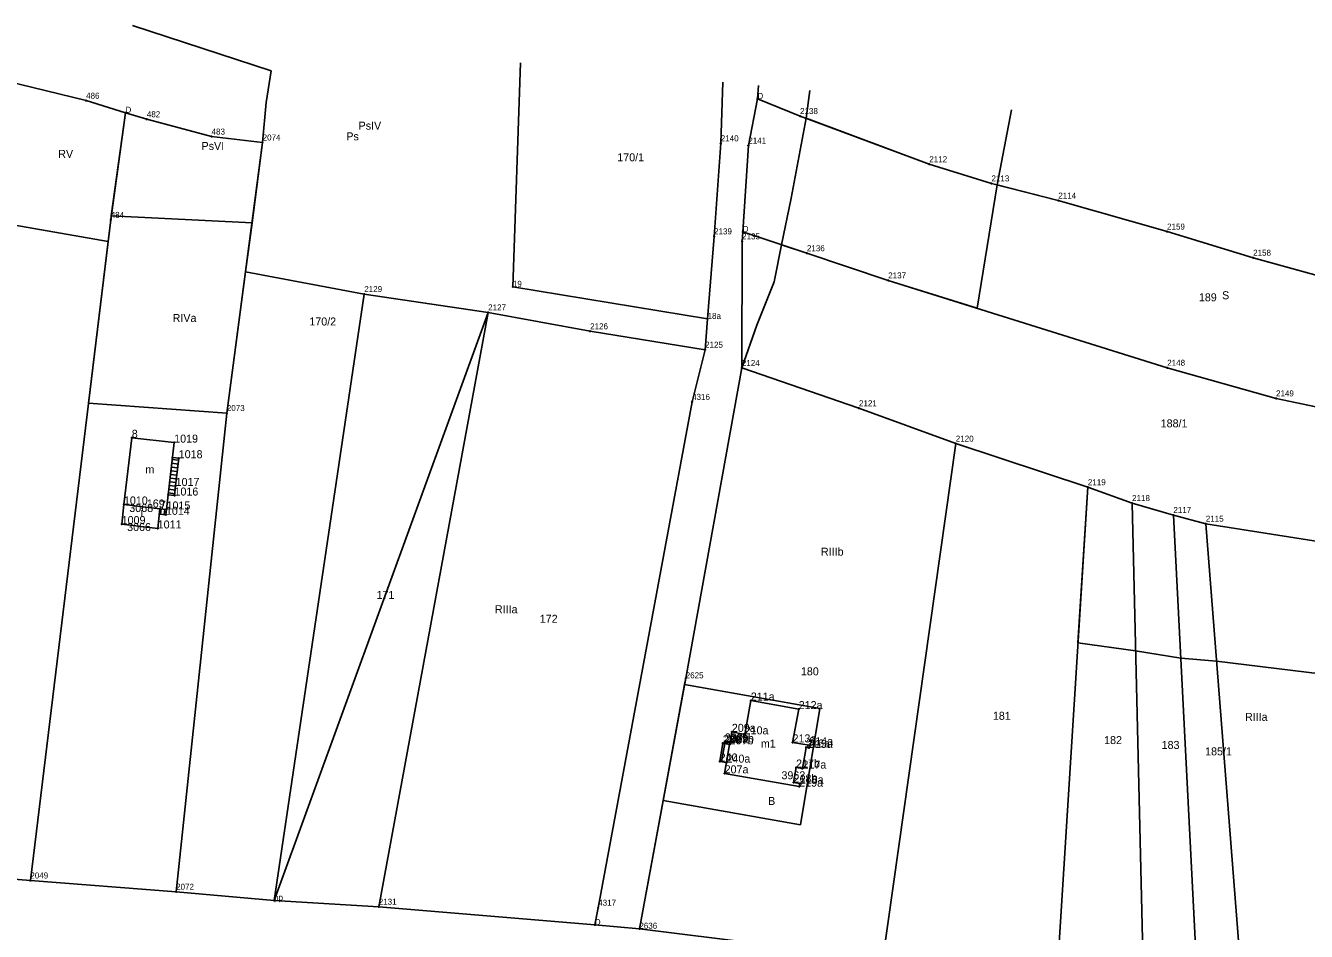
# Model space of a CAD drawing. Extents: x 7467189 to 7469366, y 5491487 to 5492734.
# Drawn here: x 7468314 to 7468554, y 5491683.5 to 5491853.3 of the extents above; entities that cross this region are included whole.
import ezdxf

# ---------------------------------------------------------------- set-up
doc = ezdxf.new("R2010")
doc.units = 0
for name, color, linetype in [('203-punkt graniczny', 7, 'Continuous'), ('203-punkt graniczny-Atr103', 7, 'Continuous'), ('209-oznaczenie konturu klasyfikacyjnego', 7, 'Continuous'), ('210-oznaczenie konturu użytku gruntowego', 7, 'Continuous'), ('211-numer działki ewidencyjnej', 7, 'Continuous'), ('217-kontur klasyfikacyjny', 7, 'Continuous'), ('218-kontur użytku gruntowego', 7, 'Continuous'), ('219-działka ewidencyjna', 7, 'Continuous'), ('312-budynek ewidencyjny', 7, 'Continuous'), ('312-oznaczenie budynku ewidencyjnego', 7, 'Continuous'), ('312-oznaczenie budynku ewidencyjnego-Atr117', 7, 'Continuous'), ('352-schody', 7, 'Continuous'), ('Punkt budynku', 7, 'Continuous'), ('Punkt budynku-Atr103', 7, 'Continuous'), ('Punkt budynku-Atr104', 7, 'Continuous')]:
    doc.layers.add(name, color=color, linetype=linetype)

# ---------------------------------------------------------------- blocks, each defined once
blk = doc.blocks.new('203')
blk.add_circle((0, 0), 0.09)
blk = doc.blocks.new('PUNKTBUD')
blk.add_circle((0, 0), 0.09)

msp = doc.modelspace()

# ---------------------------------------------------------------- linework, layer by layer
at = {"layer": '217-kontur klasyfikacyjny'}
for points in [[(7468360, 5491844.81), (7468334.03, 5491853.28)], [(7468359.08, 5491838.84), (7468360, 5491844.81)], [(7468325.31, 5491839.21), (7468305.25, 5491844.1)], [(7468444.27, 5491831.21), (7468444.64, 5491842.68)], [(7468451.37, 5491842.04), (7468451.15, 5491839.55)], [(7468460.26, 5491835.9), (7468460.95, 5491841.12)], [(7468332.7, 5491836.95), (7468325.31, 5491839.21)], [(7468358.4, 5491831.36), (7468359.08, 5491838.84)], [(7468451.15, 5491839.55), (7468449.44, 5491830.8)], [(7468498.74, 5491837.5), (7468496.08, 5491823.41)], [(7468330.03, 5491817.61), (7468332.7, 5491836.95)], [(7468332.7, 5491836.95), (7468336.69, 5491835.73)], [(7468336.69, 5491835.73), (7468348.83, 5491832.47)], [(7468457.45, 5491820.92), (7468460.26, 5491835.9)], [(7468348.83, 5491832.47), (7468358.4, 5491831.36)], [(7468358.4, 5491831.36), (7468356.41, 5491816.33)], [(7468443.02, 5491813.77), (7468444.27, 5491831.21)], [(7468449.44, 5491830.8), (7468448.39, 5491814.61)], [(7468496.08, 5491823.41), (7468492.35, 5491800.28)], [(7468455.67, 5491812.18), (7468457.45, 5491820.92)], [(7468301.54, 5491817.66), (7468329.45, 5491812.82)], [(7468329.45, 5491812.82), (7468329.93, 5491816.85)], [(7468329.93, 5491816.85), (7468330.03, 5491817.61)], [(7468356.41, 5491816.33), (7468330.03, 5491817.61)], [(7468356.41, 5491816.33), (7468355.19, 5491807.11)], [(7468441.8, 5491798.29), (7468443.02, 5491813.77)], [(7468448.39, 5491814.61), (7468448.27, 5491812.82)], [(7468329.45, 5491812.82), (7468325.75, 5491782.52)], [(7468448.27, 5491812.82), (7468448.23, 5491789.1)], [(7468454.25, 5491805.23), (7468455.67, 5491812.18)], [(7468460.42, 5491810.6), (7468455.67, 5491812.18)], [(7468475.66, 5491805.51), (7468460.42, 5491810.6)], [(7468351.69, 5491780.64), (7468355.19, 5491807.11)], [(7468355.19, 5491807.11), (7468377.45, 5491802.96)], [(7468451.04, 5491797.12), (7468454.25, 5491805.23)], [(7468492.35, 5491800.28), (7468475.66, 5491805.51)], [(7468377.45, 5491802.96), (7468400.67, 5491799.5)], [(7468400.67, 5491799.5), (7468360.54, 5491689.28)], [(7468419.79, 5491795.97), (7468400.67, 5491799.5)], [(7468441.33, 5491792.52), (7468441.8, 5491798.29)], [(7468448.23, 5491789.1), (7468451.04, 5491797.12)], [(7468441.33, 5491792.52), (7468419.79, 5491795.97)], [(7468438.9, 5491782.75), (7468441.33, 5491792.52)], [(7468448.23, 5491789.1), (7468437.7, 5491730.92)], [(7468470.18, 5491781.55), (7468448.23, 5491789.1)], [(7468325.75, 5491782.52), (7468351.69, 5491780.64)], [(7468421.3, 5491687.9), (7468438.9, 5491782.75)], [(7468488.32, 5491774.91), (7468470.18, 5491781.55)], [(7468488.32, 5491774.91), (7468474.63, 5491678.26)], [(7468513.08, 5491766.75), (7468488.32, 5491774.91)], [(7468511.23, 5491737.54), (7468513.08, 5491766.75)], [(7468521.37, 5491763.76), (7468513.08, 5491766.75)], [(7468529.11, 5491761.53), (7468521.37, 5491763.76)], [(7468535.19, 5491759.89), (7468529.11, 5491761.53)], [(7468603.08, 5491749.2), (7468535.19, 5491759.89)], [(7468522.03, 5491736.04), (7468511.23, 5491737.54)], [(7468530.49, 5491734.7), (7468522.03, 5491736.04)], [(7468537.21, 5491734.14), (7468530.49, 5491734.7)], [(7468604.7, 5491725.89), (7468537.21, 5491734.14)], [(7468437.7, 5491730.92), (7468437.49, 5491729.78)], [(7468437.49, 5491729.78), (7468462.82, 5491725.23)], [(7468462.82, 5491725.23), (7468459.23, 5491703.47)], [(7468433.47, 5491708.03), (7468429.01, 5491683.98)], [(7468459.23, 5491703.47), (7468433.47, 5491708.03)], [(7468278.14, 5491695.95), (7468314.86, 5491693.01)], [(7468314.86, 5491693.01), (7468342.18, 5491690.9)], [(7468342.18, 5491690.9), (7468360.54, 5491689.28)], [(7468360.54, 5491689.28), (7468380.16, 5491688.08)], [(7468380.16, 5491688.08), (7468420.67, 5491684.68)], [(7468420.67, 5491684.68), (7468421.3, 5491687.9)], [(7468429.01, 5491683.98), (7468474.63, 5491678.26)]]:
    msp.add_lwpolyline(points, dxfattribs=at)
at = {"layer": '218-kontur użytku gruntowego'}
for points in [[(7468305.25, 5491844.1), (7468325.31, 5491839.21)], [(7468444.27, 5491831.21), (7468444.64, 5491842.68)], [(7468451.37, 5491842.04), (7468451.15, 5491839.55)], [(7468460.26, 5491835.9), (7468460.95, 5491841.12)], [(7468325.31, 5491839.21), (7468332.7, 5491836.95)], [(7468451.15, 5491839.55), (7468449.44, 5491830.8)], [(7468332.7, 5491836.95), (7468330.03, 5491817.61)], [(7468457.45, 5491820.92), (7468460.26, 5491835.9)], [(7468483.36, 5491827.3), (7468460.26, 5491835.9)], [(7468443.02, 5491813.77), (7468444.27, 5491831.21)], [(7468449.44, 5491830.8), (7468448.39, 5491814.61)], [(7468495.01, 5491823.69), (7468483.36, 5491827.3)], [(7468496.08, 5491823.41), (7468495.01, 5491823.69)], [(7468507.54, 5491820.47), (7468496.08, 5491823.41)], [(7468455.67, 5491812.18), (7468457.45, 5491820.92)], [(7468527.92, 5491814.67), (7468507.54, 5491820.47)], [(7468330.03, 5491817.61), (7468356.41, 5491816.33)], [(7468356.41, 5491816.33), (7468355.19, 5491807.11)], [(7468441.8, 5491798.29), (7468443.02, 5491813.77)], [(7468448.39, 5491814.61), (7468448.27, 5491812.82)], [(7468544.06, 5491809.76), (7468527.92, 5491814.67)], [(7468448.27, 5491812.82), (7468448.23, 5491789.1)], [(7468454.25, 5491805.23), (7468455.67, 5491812.18)], [(7468455.67, 5491812.18), (7468460.42, 5491810.6)], [(7468460.42, 5491810.6), (7468475.66, 5491805.51)], [(7468563.32, 5491804.43), (7468544.06, 5491809.76)], [(7468355.19, 5491807.11), (7468377.45, 5491802.96)], [(7468451.04, 5491797.12), (7468454.25, 5491805.23)], [(7468475.66, 5491805.51), (7468527.96, 5491789.12)], [(7468377.45, 5491802.96), (7468400.67, 5491799.5)], [(7468400.67, 5491799.5), (7468419.79, 5491795.97)], [(7468441.33, 5491792.52), (7468441.8, 5491798.29)], [(7468448.23, 5491789.1), (7468451.04, 5491797.12)], [(7468419.79, 5491795.97), (7468441.33, 5491792.52)], [(7468438.9, 5491782.75), (7468441.33, 5491792.52)], [(7468437.7, 5491730.92), (7468448.23, 5491789.1)], [(7468527.96, 5491789.12), (7468548.35, 5491783.39)], [(7468421.3, 5491687.9), (7468438.9, 5491782.75)], [(7468548.35, 5491783.39), (7468561.18, 5491780.71)], [(7468437.49, 5491729.78), (7468433.47, 5491708.03)], [(7468437.49, 5491729.78), (7468437.7, 5491730.92)], [(7468462.82, 5491725.23), (7468437.49, 5491729.78)], [(7468459.23, 5491703.47), (7468462.82, 5491725.23)], [(7468429.01, 5491683.98), (7468433.47, 5491708.03)], [(7468433.47, 5491708.03), (7468459.23, 5491703.47)], [(7468278.14, 5491695.95), (7468314.86, 5491693.01)], [(7468314.86, 5491693.01), (7468342.18, 5491690.9)], [(7468342.18, 5491690.9), (7468360.54, 5491689.28)], [(7468360.54, 5491689.28), (7468380.16, 5491688.08)], [(7468380.16, 5491688.08), (7468420.67, 5491684.68)], [(7468420.67, 5491684.68), (7468421.3, 5491687.9)], [(7468474.63, 5491678.26), (7468429.01, 5491683.98)]]:
    msp.add_lwpolyline(points, dxfattribs=at)
at = {"layer": '219-działka ewidencyjna'}
for points in [[(7468405.31, 5491804.31), (7468406.72, 5491846.32)], [(7468305.25, 5491844.1), (7468325.31, 5491839.21)], [(7468444.27, 5491831.21), (7468444.64, 5491842.68)], [(7468451.15, 5491839.55), (7468451.37, 5491842.04)], [(7468332.7, 5491836.95), (7468325.31, 5491839.21)], [(7468451.15, 5491839.55), (7468449.44, 5491830.8)], [(7468451.15, 5491839.55), (7468459.13, 5491836.32)], [(7468332.7, 5491836.95), (7468329.93, 5491816.85)], [(7468332.7, 5491836.95), (7468336.69, 5491835.73)], [(7468336.69, 5491835.73), (7468348.83, 5491832.47)], [(7468459.13, 5491836.32), (7468483.36, 5491827.3)], [(7468348.83, 5491832.47), (7468358.4, 5491831.36)], [(7468351.69, 5491780.64), (7468358.4, 5491831.36)], [(7468443.02, 5491813.77), (7468444.27, 5491831.21)], [(7468448.39, 5491814.61), (7468449.44, 5491830.8)], [(7468483.36, 5491827.3), (7468495.01, 5491823.69)], [(7468495.01, 5491823.69), (7468507.54, 5491820.47)], [(7468507.54, 5491820.47), (7468527.92, 5491814.67)], [(7468314.86, 5491693.01), (7468329.93, 5491816.85)], [(7468441.8, 5491798.29), (7468443.02, 5491813.77)], [(7468448.27, 5491812.82), (7468448.39, 5491814.61)], [(7468448.39, 5491814.61), (7468460.42, 5491810.6)], [(7468527.92, 5491814.67), (7468544.06, 5491809.76)], [(7468448.23, 5491789.1), (7468448.27, 5491812.82)], [(7468460.42, 5491810.6), (7468475.66, 5491805.51)], [(7468544.06, 5491809.76), (7468565.4, 5491803.85)], [(7468405.31, 5491804.31), (7468441.8, 5491798.29)], [(7468475.66, 5491805.51), (7468527.96, 5491789.12)], [(7468360.54, 5491689.28), (7468377.45, 5491802.96)], [(7468377.45, 5491802.96), (7468400.67, 5491799.5)], [(7468380.16, 5491688.08), (7468400.67, 5491799.5)], [(7468400.67, 5491799.5), (7468419.79, 5491795.97)], [(7468441.8, 5491798.29), (7468441.33, 5491792.52)], [(7468419.79, 5491795.97), (7468441.33, 5491792.52)], [(7468438.9, 5491782.75), (7468441.33, 5491792.52)], [(7468437.7, 5491730.92), (7468448.23, 5491789.1)], [(7468448.23, 5491789.1), (7468470.18, 5491781.55)], [(7468527.96, 5491789.12), (7468548.35, 5491783.39)], [(7468421.3, 5491687.9), (7468438.9, 5491782.75)], [(7468548.35, 5491783.39), (7468565.6, 5491779.78)], [(7468342.18, 5491690.9), (7468351.69, 5491780.64)], [(7468470.18, 5491781.55), (7468488.32, 5491774.91)], [(7468474.63, 5491678.26), (7468488.32, 5491774.91)], [(7468488.32, 5491774.91), (7468513.08, 5491766.75)], [(7468507.3, 5491675.36), (7468513.08, 5491766.75)], [(7468513.08, 5491766.75), (7468521.37, 5491763.76)], [(7468521.37, 5491763.76), (7468523.49, 5491674.08)], [(7468521.37, 5491763.76), (7468529.11, 5491761.53)], [(7468529.11, 5491761.53), (7468533.64, 5491673.4)], [(7468529.11, 5491761.53), (7468535.19, 5491759.89)], [(7468535.19, 5491759.89), (7468542, 5491672.98)], [(7468535.19, 5491759.89), (7468603.08, 5491749.2)], [(7468429.01, 5491683.98), (7468437.7, 5491730.92)], [(7468278.14, 5491695.95), (7468314.86, 5491693.01)], [(7468314.86, 5491693.01), (7468342.18, 5491690.9)], [(7468360.54, 5491689.28), (7468342.18, 5491690.9)], [(7468360.54, 5491689.28), (7468380.16, 5491688.08)], [(7468420.67, 5491684.68), (7468380.16, 5491688.08)], [(7468420.67, 5491684.68), (7468421.3, 5491687.9)], [(7468420.67, 5491684.68), (7468429.01, 5491683.98)], [(7468429.01, 5491683.98), (7468474.63, 5491678.26)]]:
    msp.add_lwpolyline(points, dxfattribs=at)
at = {"layer": '312-budynek ewidencyjny'}
for points in [[(7468332.4, 5491763.51), (7468333.87, 5491776.01)], [(7468333.87, 5491776.01), (7468341.82, 5491775.1)], [(7468341.82, 5491775.1), (7468340.39, 5491762.57)], [(7468331.98, 5491759.83), (7468332.4, 5491763.51)], [(7468332.4, 5491763.51), (7468339.16, 5491762.71)], [(7468339.16, 5491762.71), (7468332.4, 5491763.51)], [(7468339.16, 5491762.71), (7468338.73, 5491759.01)], [(7468340.39, 5491762.57), (7468339.16, 5491762.71)], [(7468338.73, 5491759.01), (7468331.98, 5491759.83)], [(7468448.76, 5491720.41), (7468449.91, 5491726.75)], [(7468449.91, 5491726.75), (7468458.88, 5491725.14)], [(7468458.88, 5491725.14), (7468457.73, 5491718.9)], [(7468446.01, 5491718.92), (7468446.35, 5491720.88)], [(7468446.35, 5491720.88), (7468448.76, 5491720.41)], [(7468444.97, 5491718.71), (7468445.03, 5491719.09)], [(7468445.94, 5491718.53), (7468444.97, 5491718.71)], [(7468445, 5491713.1), (7468445.94, 5491718.53)], [(7468445.03, 5491719.09), (7468446.01, 5491718.92)], [(7468457.73, 5491718.9), (7468460.87, 5491718.38)], [(7468460.28, 5491717.97), (7468459.59, 5491713.99)], [(7468460.79, 5491717.88), (7468460.28, 5491717.97)], [(7468460.87, 5491718.38), (7468460.79, 5491717.88)], [(7468458.98, 5491710.61), (7468445, 5491713.1)], [(7468458.4, 5491714.19), (7468457.91, 5491711.39)], [(7468459.59, 5491713.99), (7468458.4, 5491714.19)], [(7468457.91, 5491711.39), (7468459.09, 5491711.19)], [(7468459.09, 5491711.19), (7468458.98, 5491710.61)]]:
    msp.add_lwpolyline(points, dxfattribs=at)
at = {"layer": '352-schody'}
for points in [[(7468341.5, 5491772.31), (7468342.67, 5491772.18), (7468342.09, 5491766.98), (7468341.88, 5491765.18), (7468340.7, 5491765.31)], [(7468341.5, 5491772.31), (7468342.67, 5491772.18), (7468342.09, 5491766.98), (7468341.88, 5491765.18), (7468340.7, 5491765.31)], [(7468340.39, 5491762.57), (7468340.27, 5491761.57), (7468339.04, 5491761.7), (7468339.16, 5491762.71)], [(7468340.39, 5491762.57), (7468340.27, 5491761.57), (7468339.04, 5491761.7), (7468339.16, 5491762.71)], [(7468445.35, 5491715.11), (7468444.07, 5491715.33), (7468444.66, 5491718.75), (7468444.97, 5491718.71), (7468445.94, 5491718.53)], [(7468445.35, 5491715.11), (7468444.07, 5491715.33), (7468444.66, 5491718.75), (7468444.97, 5491718.71), (7468445.94, 5491718.53)]]:
    msp.add_lwpolyline(points, close=True, dxfattribs=at)
for points in [[(7468342.47, 5491770.4), (7468341.3, 5491770.53)], [(7468342.55, 5491771.09), (7468341.38, 5491771.23)], [(7468342.63, 5491771.79), (7468341.46, 5491771.92)], [(7468342.16, 5491767.61), (7468340.98, 5491767.75)], [(7468342.24, 5491768.31), (7468341.06, 5491768.44)], [(7468342.32, 5491769), (7468341.14, 5491769.14)], [(7468342.39, 5491769.7), (7468341.22, 5491769.83)], [(7468341.92, 5491765.53), (7468340.74, 5491765.66)], [(7468342, 5491766.22), (7468340.82, 5491766.36)], [(7468342.08, 5491766.92), (7468340.9, 5491767.05)], [(7468339.35, 5491762.69), (7468339.23, 5491761.68)], [(7468340.04, 5491762.61), (7468339.93, 5491761.61)], [(7468444.42, 5491715.27), (7468445.01, 5491718.7)]]:
    msp.add_lwpolyline(points, dxfattribs=at)

# ---------------------------------------------------------------- block references
at = {"layer": '203-punkt graniczny'}
for p in [(7468325.31, 5491839.21), (7468451.15, 5491839.55), (7468332.7, 5491836.95), (7468336.69, 5491835.73), (7468459.13, 5491836.32), (7468348.83, 5491832.47), (7468358.4, 5491831.36), (7468444.27, 5491831.21), (7468449.44, 5491830.8), (7468483.36, 5491827.3), (7468495.01, 5491823.69), (7468507.54, 5491820.47), (7468329.93, 5491816.85), (7468443.02, 5491813.77), (7468448.39, 5491814.61), (7468527.92, 5491814.67), (7468448.27, 5491812.82), (7468460.42, 5491810.6), (7468544.06, 5491809.76), (7468405.31, 5491804.31), (7468475.66, 5491805.51), (7468377.45, 5491802.96), (7468400.67, 5491799.5), (7468441.8, 5491798.29), (7468419.79, 5491795.97), (7468441.33, 5491792.52), (7468448.23, 5491789.1), (7468527.96, 5491789.12), (7468438.9, 5491782.75), (7468548.35, 5491783.39), (7468351.69, 5491780.64), (7468470.18, 5491781.55), (7468488.32, 5491774.91), (7468513.08, 5491766.75), (7468521.37, 5491763.76), (7468529.11, 5491761.53), (7468535.19, 5491759.89), (7468437.7, 5491730.92), (7468314.86, 5491693.01), (7468342.18, 5491690.9), (7468360.54, 5491689.28), (7468380.16, 5491688.08), (7468421.3, 5491687.9), (7468420.67, 5491684.68), (7468429.01, 5491683.98)]:
    msp.add_blockref('203', p, dxfattribs=at)
at = {"layer": 'Punkt budynku'}
for p in [(7468333.87, 5491776.01), (7468341.82, 5491775.1), (7468341.5, 5491772.31), (7468342.67, 5491772.18), (7468340.7, 5491765.31), (7468341.88, 5491765.18), (7468342.09, 5491766.98), (7468332.4, 5491763.51), (7468339.04, 5491761.7), (7468339.16, 5491762.71), (7468340.27, 5491761.57), (7468340.39, 5491762.57), (7468331.98, 5491759.83), (7468338.73, 5491759.01), (7468449.91, 5491726.75), (7468458.88, 5491725.14), (7468446.35, 5491720.88), (7468448.76, 5491720.41), (7468444.66, 5491718.75), (7468444.97, 5491718.71), (7468445.03, 5491719.09), (7468445.94, 5491718.53), (7468446.01, 5491718.92), (7468457.73, 5491718.9), (7468460.28, 5491717.97), (7468460.79, 5491717.88), (7468460.87, 5491718.38), (7468444.07, 5491715.33), (7468445.35, 5491715.11), (7468445, 5491713.1), (7468458.4, 5491714.19), (7468459.59, 5491713.99), (7468457.91, 5491711.39), (7468458.98, 5491710.61), (7468459.09, 5491711.19)]:
    msp.add_blockref('PUNKTBUD', p, dxfattribs=at)

# ---------------------------------------------------------------- texts
at = {"layer": '203-punkt graniczny-Atr103'}
for s, height, p in [('486', 1.125, (7468325.31, 5491839.58)), ('D', 1.12, (7468451.15, 5491839.55)), ('D', 1.12, (7468332.7, 5491836.95)), ('2138', 1.125, (7468459.13, 5491836.7)), ('482', 1.125, (7468336.69, 5491836.11)), ('483', 1.125, (7468348.83, 5491832.85)), ('2074', 1.125, (7468358.4, 5491831.74)), ('2140', 1.125, (7468444.27, 5491831.58)), ('2141', 1.125, (7468449.44, 5491831.17)), ('2112', 1.125, (7468483.36, 5491827.67)), ('2113', 1.125, (7468495.01, 5491824.07)), ('2114', 1.125, (7468507.54, 5491820.85)), ('484', 1.125, (7468329.93, 5491817.23)), ('D', 1.12, (7468448.39, 5491814.61)), ('2159', 1.125, (7468527.92, 5491815.04)), ('2139', 1.125, (7468443.02, 5491814.14)), ('2135', 1.125, (7468448.27, 5491813.2)), ('2136', 1.125, (7468460.42, 5491810.98)), ('2158', 1.125, (7468544.06, 5491810.14)), ('2137', 1.125, (7468475.66, 5491805.89)), ('2129', 1.125, (7468377.45, 5491803.33)), ('19', 1.125, (7468405.31, 5491804.31)), ('2127', 1.125, (7468400.67, 5491799.88)), ('18a', 1.125, (7468441.8, 5491798.29)), ('2126', 1.125, (7468419.79, 5491796.35)), ('2125', 1.125, (7468441.33, 5491792.89)), ('2124', 1.125, (7468448.23, 5491789.48)), ('2148', 1.125, (7468527.96, 5491789.5)), ('2149', 1.125, (7468548.35, 5491783.77)), ('2073', 1.125, (7468351.69, 5491781.02)), ('4316', 1.125, (7468438.9, 5491783.12)), ('2121', 1.125, (7468470.18, 5491781.92)), ('2120', 1.125, (7468488.32, 5491775.29)), ('2119', 1.125, (7468513.08, 5491767.12)), ('2118', 1.125, (7468521.37, 5491764.14)), ('2117', 1.125, (7468529.11, 5491761.91)), ('2115', 1.125, (7468535.19, 5491760.27)), ('2625', 1.125, (7468437.7, 5491730.92)), ('2049', 1.125, (7468314.86, 5491693.39)), ('2072', 1.125, (7468342.18, 5491691.28)), ('pp', 1.125, (7468360.54, 5491689.28)), ('2131', 1.125, (7468380.16, 5491688.46)), ('4317', 1.125, (7468421.3, 5491688.28)), ('D', 1.12, (7468420.67, 5491684.68)), ('2636', 1.125, (7468429.01, 5491683.98))]:
    msp.add_text(s, height=height, dxfattribs=at).set_placement(p)
at = {"layer": '209-oznaczenie konturu klasyfikacyjnego'}
for s, p in [('PsIV', (7468376.39, 5491833.77)), ('PsVI', (7468346.95, 5491829.96)), ('RV', (7468320.09, 5491828.48)), ('RIVa', (7468341.53, 5491797.72)), ('RIIIb', (7468463.05, 5491753.91)), ('RIIIa', (7468401.94, 5491743.11)), ('RIIIa', (7468542.53, 5491722.94))]:
    msp.add_text(s, height=1.5, dxfattribs=at).set_placement(p)
at = {"layer": '210-oznaczenie konturu użytku gruntowego'}
for s, p in [('Ps', (7468374.09, 5491831.77)), ('S', (7468538.25, 5491801.98)), ('B', (7468453.15, 5491707.17))]:
    msp.add_text(s, height=1.5, dxfattribs=at).set_placement(p)
at = {"layer": '211-numer działki ewidencyjnej'}
for s, p in [('170/1', (7468424.88, 5491827.84)), ('189', (7468533.89, 5491801.59)), ('170/2', (7468367.16, 5491797.06)), ('188/1', (7468526.73, 5491777.96)), ('169', (7468336.69, 5491762.94)), ('171', (7468379.75, 5491745.8)), ('172', (7468410.34, 5491741.33)), ('180', (7468459.29, 5491731.47)), ('181', (7468495.28, 5491723.14)), ('182', (7468516.13, 5491718.59)), ('183', (7468526.91, 5491717.68)), ('185/1', (7468535.06, 5491716.47))]:
    msp.add_text(s, height=1.5, dxfattribs=at).set_placement(p)
at = {"layer": '312-oznaczenie budynku ewidencyjnego'}
for s, p in [('3068', (7468333.41, 5491762.1)), ('3066', (7468333, 5491758.53)), ('3962', (7468455.65, 5491711.99))]:
    msp.add_text(s, height=1.5, dxfattribs=at).set_placement(p)
at = {"layer": '312-oznaczenie budynku ewidencyjnego-Atr117'}
for s, p in [('m', (7468336.42, 5491769.33)), ('i', (7468335.52, 5491761.29)), ('m1', (7468451.79, 5491717.94))]:
    msp.add_text(s, height=1.5, dxfattribs=at).set_placement(p)
at = {"layer": 'Punkt budynku-Atr103'}
for s, p in [('1019', (7468341.82, 5491775.1)), ('1010', (7468332.4, 5491763.51)), ('1015', (7468340.39, 5491762.57)), ('1009', (7468331.98, 5491759.83)), ('1011', (7468338.73, 5491759.01)), ('211a', (7468449.91, 5491726.75)), ('212a', (7468458.88, 5491725.14)), ('209a', (7468446.35, 5491720.88)), ('208a', (7468444.97, 5491718.71)), ('208b', (7468445.03, 5491719.09)), ('207b', (7468445.94, 5491718.53)), ('209b', (7468446.01, 5491718.92)), ('210a', (7468448.76, 5491720.41)), ('213a', (7468457.73, 5491718.9)), ('214a', (7468460.87, 5491718.38)), ('216a', (7468460.28, 5491717.97)), ('215a', (7468460.79, 5491717.88)), ('217b', (7468458.4, 5491714.19)), ('217a', (7468459.59, 5491713.99)), ('207a', (7468445, 5491713.1)), ('218b', (7468457.91, 5491711.39)), ('218a', (7468459.09, 5491711.19)), ('219a', (7468458.98, 5491710.61))]:
    msp.add_text(s, height=1.5, dxfattribs=at).set_placement(p)
at = {"layer": 'Punkt budynku-Atr104'}
for s, p in [('8', (7468333.87, 5491776.01)), ('1018', (7468342.67, 5491772.18)), ('1017', (7468342.09, 5491766.98)), ('1016', (7468341.88, 5491765.18)), ('7', (7468339.16, 5491762.71)), ('1014', (7468340.27, 5491761.57)), ('239', (7468444.66, 5491718.75)), ('240', (7468444.07, 5491715.33)), ('240a', (7468445.35, 5491715.11))]:
    msp.add_text(s, height=1.5, dxfattribs=at).set_placement(p)

doc.saveas('drawing.dxf')
